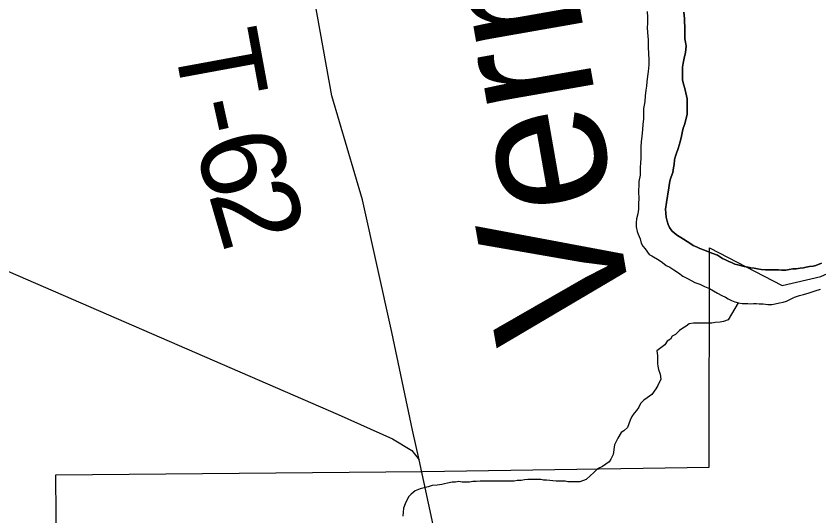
# Model space of a CAD drawing. Extents: x 0 to 34, y 0 to 22.
# Drawn here: x 3.337 to 3.877, y 18.57 to 18.906 of the extents above; entities that cross this region are included whole.
import ezdxf

# ---------------------------------------------------------------- set-up
doc = ezdxf.new("R2010")
doc.units = 0
for name, color, linetype in [('GM_X_City_Street', 7, 'Continuous'), ('GM_X_Corporation', 7, 'Continuous'), ('GM_X_Major_River', 7, 'Continuous'), ('GM_X_Major_River_Text', 7, 'Continuous'), ('GM_X_Minor_River', 7, 'Continuous'), ('GM_X_Township_Road', 7, 'Continuous'), ('GM_X_Township_Road_Text', 7, 'Continuous')]:
    doc.layers.add(name, color=color, linetype=linetype)

msp = doc.modelspace()

# ---------------------------------------------------------------- linework, layer by layer
at = {"layer": 'GM_X_City_Street'}
msp.add_lwpolyline([(3.65884, 18.33325), (3.65666, 18.38408), (3.65315, 18.38475), (3.64914, 18.38676), (3.64579, 18.39278), (3.64395, 18.40097), (3.64412, 18.41953), (3.64563, 18.4309), (3.64345, 18.43943), (3.63325, 18.49143), (3.60823, 18.60774)], dxfattribs=at)
at = {"layer": 'GM_X_Corporation'}
msp.add_lwpolyline([(3.36584, 18.37932), (3.36394, 18.59773), (3.61027, 18.5999), (3.80297, 18.60274), (3.80315, 18.75008), (3.85204, 18.72478), (3.87805, 18.73079), (3.98865, 18.78045), (4.05384, 18.75639), (4.04801, 18.71374), (4.03064, 18.62437), (4.02836, 18.60896), (4.13901, 18.61178), (4.41179, 18.61588), (4.4162, 18.43931)], dxfattribs=at)
at = {"layer": 'GM_X_Major_River'}
for points in [[(3.76125, 18.90867), (3.76163, 18.90486), (3.76162, 18.90068), (3.76124, 18.89802), (3.76162, 18.89459), (3.76199, 18.88965), (3.76199, 18.8847), (3.76236, 18.87634), (3.76235, 18.87291), (3.76197, 18.86835), (3.76158, 18.86531), (3.7612, 18.86151), (3.76082, 18.85846), (3.76044, 18.8558), (3.76005, 18.852), (3.75967, 18.8482), (3.75928, 18.84591), (3.7589, 18.84363), (3.7589, 18.84059), (3.75889, 18.83641), (3.75851, 18.83298), (3.75813, 18.82918), (3.75774, 18.825), (3.75736, 18.82119), (3.75697, 18.81777), (3.75697, 18.81473), (3.75697, 18.81055), (3.75696, 18.80674), (3.75658, 18.80446), (3.75658, 18.80256), (3.75657, 18.79876), (3.75581, 18.79457), (3.75581, 18.79153), (3.75542, 18.78925), (3.75542, 18.78659), (3.7558, 18.7843), (3.7558, 18.7824), (3.75541, 18.7805), (3.75541, 18.7786), (3.75541, 18.77594), (3.75503, 18.7729), (3.75426, 18.76947), (3.75388, 18.76681), (3.75388, 18.76415), (3.75463, 18.76111), (3.75539, 18.7592), (3.75653, 18.75616), (3.75729, 18.75312), (3.75842, 18.75121), (3.75994, 18.74931), (3.7626, 18.74551), (3.76449, 18.74474), (3.76943, 18.7417), (3.77171, 18.74017), (3.77399, 18.73827), (3.77664, 18.73713), (3.7793, 18.73522), (3.78234, 18.73332), (3.78538, 18.73103), (3.7888, 18.72913)], [(3.76125, 18.90867), (3.76163, 18.90486), (3.76162, 18.90068), (3.76124, 18.89802), (3.76162, 18.89459), (3.76199, 18.88965), (3.76199, 18.8847), (3.76236, 18.87634), (3.76235, 18.87291), (3.76197, 18.86835), (3.76158, 18.86531), (3.7612, 18.86151), (3.76082, 18.85846), (3.76044, 18.8558), (3.76005, 18.852), (3.75967, 18.8482), (3.75928, 18.84591), (3.7589, 18.84363), (3.7589, 18.84059), (3.75889, 18.83641), (3.75851, 18.83298), (3.75813, 18.82918), (3.75774, 18.825), (3.75736, 18.82119), (3.75697, 18.81777), (3.75697, 18.81473), (3.75697, 18.81055), (3.75696, 18.80674), (3.75658, 18.80446), (3.75658, 18.80256), (3.75657, 18.79876), (3.75581, 18.79457), (3.75581, 18.79153), (3.75542, 18.78925), (3.75542, 18.78659), (3.7558, 18.7843), (3.7558, 18.7824), (3.75541, 18.7805), (3.75541, 18.7786), (3.75541, 18.77594), (3.75503, 18.7729), (3.75426, 18.76947), (3.75388, 18.76681), (3.75388, 18.76415), (3.75463, 18.76111), (3.75539, 18.7592), (3.75653, 18.75616), (3.75729, 18.75312), (3.75842, 18.75121), (3.75994, 18.74931), (3.7626, 18.74551), (3.76449, 18.74474), (3.76943, 18.7417), (3.77171, 18.74017), (3.77399, 18.73827), (3.77664, 18.73713), (3.7793, 18.73522), (3.78234, 18.73332), (3.78538, 18.73103), (3.7888, 18.72913)], [(3.78996, 18.75309), (3.78389, 18.7569), (3.78161, 18.75842), (3.77971, 18.75994), (3.77781, 18.76147), (3.7763, 18.76375), (3.77554, 18.76565), (3.77478, 18.76794), (3.77402, 18.7706), (3.77365, 18.77592), (3.77441, 18.78048), (3.77594, 18.79037), (3.77633, 18.79341), (3.77671, 18.7957), (3.77747, 18.7976), (3.77861, 18.80064), (3.779, 18.80368), (3.77938, 18.80596), (3.77976, 18.80901), (3.78015, 18.81091), (3.78091, 18.81281), (3.78205, 18.81661), (3.78358, 18.82117), (3.78434, 18.82498), (3.7851, 18.8284), (3.78548, 18.8303), (3.78663, 18.83334), (3.78815, 18.8398), (3.78817, 18.85007), (3.78665, 18.85692), (3.7859, 18.8592), (3.78514, 18.86263), (3.78514, 18.86567), (3.78515, 18.86909), (3.78515, 18.87137), (3.78553, 18.87404), (3.7863, 18.87746), (3.78706, 18.88126), (3.78745, 18.88544), (3.78707, 18.88811), (3.78669, 18.89039), (3.78669, 18.89267), (3.7867, 18.89533), (3.7867, 18.89838), (3.78632, 18.9018), (3.78633, 18.90408), (3.78595, 18.90826)], [(3.78595, 18.90826), (3.78633, 18.90408), (3.78632, 18.9018), (3.7867, 18.89838), (3.7867, 18.89533), (3.78669, 18.89267), (3.78669, 18.89039), (3.78707, 18.88811), (3.78745, 18.88544), (3.78706, 18.88126), (3.7863, 18.87746), (3.78553, 18.87404), (3.78515, 18.87137), (3.78515, 18.86909), (3.78514, 18.86567), (3.78514, 18.86263), (3.7859, 18.8592), (3.78665, 18.85692), (3.78817, 18.85007), (3.78815, 18.8398), (3.78663, 18.83334), (3.78548, 18.8303), (3.7851, 18.8284), (3.78434, 18.82498), (3.78358, 18.82117), (3.78205, 18.81661), (3.78091, 18.81281), (3.78015, 18.81091), (3.77976, 18.80901), (3.77938, 18.80596), (3.779, 18.80368), (3.77861, 18.80064), (3.77747, 18.7976), (3.77671, 18.7957), (3.77633, 18.79341), (3.77594, 18.79037), (3.77441, 18.78048), (3.77365, 18.77592), (3.77402, 18.7706), (3.77478, 18.76794), (3.77554, 18.76565), (3.7763, 18.76375), (3.77781, 18.76147), (3.77971, 18.75994), (3.78161, 18.75842), (3.78389, 18.7569), (3.78996, 18.75309)], [(3.87848, 18.73971), (3.87468, 18.73819), (3.87278, 18.73781), (3.8705, 18.73743), (3.86822, 18.73705), (3.86632, 18.73667), (3.86404, 18.7363), (3.86138, 18.73592), (3.8591, 18.73592), (3.85682, 18.73554), (3.85454, 18.73516), (3.85188, 18.73516), (3.8496, 18.73517), (3.8458, 18.73517), (3.8439, 18.73517), (3.84086, 18.73517), (3.83782, 18.73555), (3.83554, 18.73594), (3.83326, 18.73632), (3.83098, 18.7367), (3.82908, 18.73708), (3.82642, 18.73747), (3.82224, 18.73861), (3.82034, 18.73899), (3.81807, 18.74013), (3.81617, 18.7409), (3.81389, 18.74204), (3.81199, 18.7428), (3.80857, 18.74509), (3.80553, 18.74623), (3.8025, 18.74737), (3.79983, 18.74852), (3.7968, 18.74966), (3.7949, 18.75042), (3.79224, 18.75157), (3.78996, 18.75309)], [(3.78996, 18.75309), (3.79224, 18.75157), (3.7949, 18.75042), (3.7968, 18.74966), (3.79983, 18.74852), (3.8025, 18.74737), (3.80553, 18.74623), (3.80857, 18.74509), (3.81199, 18.7428), (3.81389, 18.74204), (3.81617, 18.7409), (3.81807, 18.74013), (3.82034, 18.73899), (3.82224, 18.73861), (3.82642, 18.73747), (3.82908, 18.73708), (3.83098, 18.7367), (3.83326, 18.73632), (3.83554, 18.73594), (3.83782, 18.73555), (3.84086, 18.73517), (3.8439, 18.73517), (3.8458, 18.73517), (3.8496, 18.73517), (3.85188, 18.73516), (3.85454, 18.73516), (3.85682, 18.73554), (3.8591, 18.73592), (3.86138, 18.73592), (3.86404, 18.7363), (3.86632, 18.73667), (3.86822, 18.73705), (3.8705, 18.73743), (3.87278, 18.73781), (3.87468, 18.73819), (3.87848, 18.73971)], [(3.7888, 18.72913), (3.79335, 18.72684), (3.79677, 18.7257), (3.79981, 18.72418), (3.80323, 18.72265), (3.80589, 18.72113), (3.80854, 18.71961), (3.81158, 18.71808), (3.81386, 18.71694), (3.81576, 18.7158), (3.81804, 18.71465), (3.82032, 18.71389), (3.82259, 18.71313), (3.82525, 18.71275), (3.82715, 18.71274), (3.82905, 18.71274), (3.83095, 18.71236), (3.83285, 18.71274), (3.83475, 18.71274), (3.83665, 18.71236), (3.83931, 18.71235), (3.84235, 18.71197), (3.84501, 18.71197), (3.84729, 18.71235), (3.85033, 18.71311), (3.85261, 18.71348), (3.85489, 18.71424), (3.85718, 18.71538), (3.86022, 18.7169), (3.86364, 18.71804), (3.8663, 18.7188), (3.8701, 18.71994), (3.87428, 18.72107), (3.8777, 18.72221)], [(3.7888, 18.72913), (3.79335, 18.72684), (3.79677, 18.7257), (3.79981, 18.72418), (3.80323, 18.72265), (3.80589, 18.72113), (3.80854, 18.71961), (3.81158, 18.71808), (3.81386, 18.71694), (3.81576, 18.7158), (3.81804, 18.71465), (3.82032, 18.71389), (3.82259, 18.71313), (3.82525, 18.71275), (3.82715, 18.71274), (3.82905, 18.71274), (3.83095, 18.71236), (3.83285, 18.71274), (3.83475, 18.71274), (3.83665, 18.71236), (3.83931, 18.71235), (3.84235, 18.71197), (3.84501, 18.71197), (3.84729, 18.71235), (3.85033, 18.71311), (3.85261, 18.71348), (3.85489, 18.71424), (3.85718, 18.71538), (3.86022, 18.7169), (3.86364, 18.71804), (3.8663, 18.7188), (3.8701, 18.71994), (3.87428, 18.72107), (3.8777, 18.72221)]]:
    msp.add_lwpolyline(points, dxfattribs=at)
at = {"layer": 'GM_X_Minor_River'}
for points in [[(3.82258, 18.71313), (3.81574, 18.70173), (3.8127, 18.70059), (3.81042, 18.70021), (3.807, 18.69983), (3.80472, 18.69945), (3.80244, 18.69945), (3.79902, 18.69946), (3.79636, 18.69946), (3.79446, 18.69946), (3.79256, 18.69946), (3.78952, 18.69908), (3.78762, 18.69756), (3.78534, 18.69605), (3.78306, 18.69453), (3.7804, 18.69187), (3.77812, 18.69073), (3.77697, 18.68883), (3.77469, 18.6873), (3.77317, 18.68503), (3.76784, 18.68085), (3.76822, 18.6778), (3.76822, 18.67248), (3.76859, 18.67058), (3.76897, 18.66829), (3.77011, 18.66525), (3.77048, 18.66183), (3.76858, 18.65765), (3.76706, 18.65537), (3.76439, 18.65156), (3.76135, 18.64929), (3.75907, 18.64776), (3.75679, 18.64548), (3.75564, 18.6432), (3.75412, 18.64092), (3.7526, 18.63902), (3.75108, 18.63674), (3.74994, 18.63446), (3.74803, 18.62952), (3.74575, 18.62724), (3.74385, 18.6261), (3.74156, 18.6223), (3.74042, 18.62002), (3.73928, 18.61774), (3.73851, 18.61127), (3.73699, 18.60823), (3.73585, 18.60633), (3.73357, 18.60481), (3.73128, 18.60329), (3.72786, 18.60177), (3.7252, 18.59911), (3.7233, 18.59721), (3.72026, 18.59455), (3.71607, 18.59303), (3.71418, 18.59304), (3.7119, 18.59304), (3.70999, 18.59304), (3.70809, 18.59304), (3.70619, 18.59342), (3.7043, 18.59342), (3.7024, 18.59343), (3.70012, 18.59343), (3.69366, 18.59419), (3.69176, 18.59419), (3.68986, 18.59458), (3.6872, 18.59458), (3.6853, 18.59458), (3.6834, 18.59458), (3.68112, 18.59458), (3.67884, 18.59421), (3.67656, 18.59383), (3.6739, 18.59383), (3.672, 18.59345), (3.66972, 18.59345), (3.66782, 18.59345), (3.66554, 18.59346), (3.66288, 18.59346), (3.66022, 18.59346), (3.65832, 18.59346), (3.65566, 18.59346), (3.653, 18.59347), (3.6511, 18.59347), (3.6492, 18.59347), (3.64654, 18.59309), (3.64426, 18.59309), (3.64198, 18.59271), (3.63932, 18.59272), (3.63704, 18.59272), (3.63476, 18.5931), (3.63248, 18.59272), (3.6302, 18.59272), (3.62716, 18.59197)], [(3.62716, 18.59197), (3.62526, 18.59159), (3.62336, 18.59121), (3.62032, 18.59083), (3.6169, 18.59045), (3.61424, 18.58969), (3.60892, 18.58818), (3.6055, 18.58704), (3.60283, 18.58476), (3.60093, 18.58286), (3.59865, 18.5783), (3.59751, 18.57526), (3.59712, 18.56993)]]:
    msp.add_lwpolyline(points, dxfattribs=at)
at = {"layer": 'GM_X_Township_Road'}
for points in [[(3.60823, 18.60774), (3.60373, 18.6276), (3.58981, 18.69351), (3.57016, 18.78235), (3.54955, 18.85212), (3.5225, 19.00157), (3.4951, 19.15824), (3.48582, 19.20387), (3.48509, 19.21186), (3.48591, 19.22668), (3.49406, 19.27111), (3.51882, 19.38578), (3.54729, 19.57149), (3.58018, 19.81724), (3.587, 19.87766)], [(2.1, 18.87394), (2.35622, 18.87297), (2.67326, 18.87405), (2.82988, 18.87345), (2.8879, 18.87171), (2.98156, 18.87137), (3.01038, 18.87125), (3.01834, 18.87047), (3.03992, 18.86088), (3.55378, 18.63824), (3.59022, 18.62186), (3.60332, 18.61408), (3.60823, 18.60774)]]:
    msp.add_lwpolyline(points, dxfattribs=at)

# ---------------------------------------------------------------- texts
at = {"layer": 'GM_X_Major_River_Text'}
msp.add_text('Vermilion', height=0.094755, rotation=99.9481, dxfattribs=at).set_placement((3.75359, 18.69837))
at = {"layer": 'GM_X_Township_Road_Text'}
for s, rotation, p in [('T', 280.4198, (3.44266, 18.8905)), ('-', 282.4744, (3.45079, 18.84652)), ('6', 285.9626, (3.45676, 18.82008)), ('2', 286.2183, (3.46646, 18.78617))]:
    msp.add_text(s, height=0.05682, rotation=rotation, dxfattribs=at).set_placement(p)

doc.saveas('drawing.dxf')
